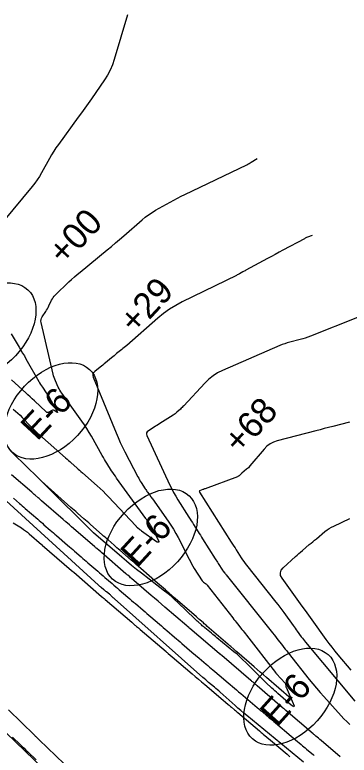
# Model space of a CAD drawing. Extents: x 1005228 to 1008882, y 1883389 to 1885754.
# Drawn here: x 1007166.4 to 1007247.3, y 1885273.6 to 1885452.9 of the extents above; entities that cross this region are included whole.
import ezdxf

# ---------------------------------------------------------------- set-up
doc = ezdxf.new("R2010")
doc.units = 0
for name, color, linetype in [('C-ANNO-NOTE', 7, 'Continuous'), ('R_Erosion', 7, 'Continuous'), ('S_BASELINE', 7, 'Continuous'), ('S_BRIDGE', 7, 'Continuous'), ('TSOBSTACLE', 7, 'Continuous')]:
    doc.layers.add(name, color=color, linetype=linetype)

msp = doc.modelspace()

# ---------------------------------------------------------------- linework, layer by layer
at = {"layer": 'C-ANNO-NOTE'}
for points in [[(1007193.66, 1885452.89), (1007190.46, 1885442.04), (1007190.02, 1885440.74), (1007189.48, 1885439.48), (1007188.84, 1885438.28), (1007188.1, 1885437.12), (1007184.96, 1885432.57), (1007184.17, 1885431.44), (1007183.37, 1885430.31), (1007182.57, 1885429.19), (1007181.75, 1885428.07), (1007176.93, 1885421.48), (1007176.35, 1885420.66), (1007175.8, 1885419.83), (1007175.28, 1885418.98), (1007174.78, 1885418.11), (1007172.83, 1885414.62), (1007172.33, 1885413.76), (1007171.78, 1885412.92), (1007171.2, 1885412.11), (1007170.59, 1885411.33), (1007163.58, 1885402.82)], [(1007166.02, 1885357.41), (1007166.58, 1885356.93), (1007167.14, 1885356.43), (1007167.67, 1885355.92), (1007168.19, 1885355.39), (1007170.24, 1885353.23), (1007170.76, 1885352.69), (1007171.28, 1885352.17), (1007171.83, 1885351.66), (1007172.38, 1885351.17), (1007178.7, 1885345.6), (1007179.04, 1885345.31), (1007179.38, 1885345.01), (1007179.72, 1885344.71), (1007180.05, 1885344.41), (1007181.4, 1885343.21), (1007181.73, 1885342.91), (1007182.07, 1885342.62), (1007182.41, 1885342.32), (1007182.74, 1885342.02), (1007186.34, 1885338.81), (1007187.05, 1885338.17), (1007187.74, 1885337.51), (1007188.41, 1885336.84), (1007189.07, 1885336.16), (1007195.67, 1885329.19), (1007195.7, 1885329.15), (1007195.74, 1885329.11), (1007195.77, 1885329.07), (1007195.8, 1885329.03), (1007195.93, 1885328.86), (1007195.96, 1885328.82), (1007196, 1885328.79), (1007196.04, 1885328.75), (1007196.08, 1885328.72), (1007196.64, 1885328.3), (1007196.75, 1885328.22), (1007196.86, 1885328.14), (1007196.97, 1885328.06), (1007197.08, 1885327.98), (1007200.65, 1885325.37), (1007200.71, 1885325.33), (1007200.78, 1885325.3), (1007200.84, 1885325.28), (1007200.92, 1885325.27), (1007201.21, 1885325.24), (1007201.27, 1885325.24), (1007201.3, 1885325.26), (1007201.31, 1885325.3), (1007201.29, 1885325.36), (1007199.48, 1885328.88), (1007199.39, 1885329.06), (1007199.28, 1885329.24), (1007199.17, 1885329.42), (1007199.05, 1885329.6), (1007198.57, 1885330.28), (1007198.45, 1885330.45), (1007198.32, 1885330.62), (1007198.2, 1885330.79), (1007198.08, 1885330.96), (1007191.04, 1885340.7), (1007190.73, 1885341.14), (1007190.42, 1885341.59), (1007190.12, 1885342.04), (1007189.83, 1885342.49), (1007188.66, 1885344.32), (1007188.37, 1885344.77), (1007188.09, 1885345.24), (1007187.82, 1885345.7), (1007187.55, 1885346.17), (1007184.95, 1885350.85), (1007184.41, 1885351.78), (1007183.85, 1885352.69), (1007183.27, 1885353.59), (1007182.65, 1885354.46), (1007177.76, 1885361.28), (1007177.52, 1885361.63), (1007177.3, 1885361.99), (1007177.1, 1885362.36), (1007176.92, 1885362.74), (1007176.22, 1885364.29), (1007176.05, 1885364.69), (1007175.91, 1885365.08), (1007175.78, 1885365.49), (1007175.68, 1885365.9), (1007172.77, 1885378.35), (1007172.72, 1885378.72), (1007172.74, 1885379.08), (1007172.84, 1885379.42), (1007173.02, 1885379.75), (1007173.87, 1885381.04), (1007174.08, 1885381.37), (1007174.28, 1885381.7), (1007174.46, 1885382.04), (1007174.63, 1885382.39), (1007175.3, 1885383.79), (1007175.48, 1885384.13), (1007175.69, 1885384.45), (1007175.92, 1885384.75), (1007176.19, 1885385.03), (1007179.5, 1885388.21), (1007180.15, 1885388.82), (1007180.82, 1885389.42), (1007181.49, 1885390.01), (1007182.17, 1885390.58), (1007188.74, 1885395.98), (1007189.76, 1885396.82), (1007190.76, 1885397.66), (1007191.76, 1885398.51), (1007192.76, 1885399.37), (1007197.19, 1885403.24), (1007197.96, 1885403.88), (1007198.76, 1885404.48), (1007199.6, 1885405.03), (1007200.46, 1885405.55), (1007203.97, 1885407.53), (1007204.85, 1885408.02), (1007205.74, 1885408.49), (1007206.63, 1885408.95), (1007207.54, 1885409.4), (1007222.54, 1885416.6), (1007222.81, 1885416.74), (1007223.07, 1885416.88), (1007223.32, 1885417.02), (1007223.57, 1885417.18), (1007225.07, 1885418.12)], [(1007238.33, 1885399.47), (1007237.2, 1885399.03), (1007237.01, 1885398.95), (1007236.83, 1885398.86), (1007236.65, 1885398.78), (1007236.47, 1885398.68), (1007231.27, 1885395.88), (1007230.34, 1885395.38), (1007229.42, 1885394.88), (1007228.49, 1885394.38), (1007227.57, 1885393.88), (1007222.31, 1885391.04), (1007222.12, 1885390.93), (1007221.93, 1885390.83), (1007221.74, 1885390.72), (1007221.55, 1885390.62), (1007220.79, 1885390.19), (1007220.6, 1885390.09), (1007220.41, 1885389.99), (1007220.22, 1885389.89), (1007220.03, 1885389.79), (1007206.93, 1885383.38), (1007205.35, 1885382.54), (1007203.83, 1885381.6), (1007202.38, 1885380.56), (1007200.99, 1885379.42), (1007193.47, 1885372.82), (1007193.17, 1885372.56), (1007192.87, 1885372.31), (1007192.57, 1885372.06), (1007192.26, 1885371.81), (1007191.03, 1885370.84), (1007190.72, 1885370.6), (1007190.42, 1885370.35), (1007190.12, 1885370.1), (1007189.82, 1885369.85), (1007188.37, 1885368.61), (1007188.04, 1885368.34), (1007187.72, 1885368.07), (1007187.39, 1885367.8), (1007187.06, 1885367.54), (1007185.73, 1885366.49), (1007185.46, 1885366.21), (1007185.31, 1885365.9), (1007185.29, 1885365.56), (1007185.39, 1885365.18), (1007190.89, 1885351.68), (1007191.38, 1885350.51), (1007191.9, 1885349.35), (1007192.45, 1885348.21), (1007193.02, 1885347.07), (1007196.19, 1885341.01), (1007196.37, 1885340.66), (1007196.56, 1885340.33), (1007196.76, 1885339.99), (1007196.97, 1885339.66), (1007197.95, 1885338.12), (1007198.09, 1885337.91), (1007198.23, 1885337.7), (1007198.37, 1885337.49), (1007198.52, 1885337.29), (1007199.11, 1885336.47), (1007199.25, 1885336.27), (1007199.4, 1885336.06), (1007199.55, 1885335.86), (1007199.69, 1885335.65), (1007203.47, 1885330.3), (1007204.14, 1885329.33), (1007204.76, 1885328.34), (1007205.35, 1885327.32), (1007205.9, 1885326.29), (1007208.58, 1885321.06), (1007208.88, 1885320.5), (1007209.18, 1885319.95), (1007209.5, 1885319.4), (1007209.83, 1885318.86), (1007211.7, 1885315.87), (1007211.78, 1885315.76), (1007211.87, 1885315.66), (1007211.97, 1885315.57), (1007212.08, 1885315.49), (1007212.54, 1885315.18), (1007212.65, 1885315.1), (1007212.75, 1885315.01), (1007212.85, 1885314.91), (1007212.93, 1885314.81), (1007219.15, 1885306.85), (1007219.42, 1885306.5), (1007219.7, 1885306.15), (1007219.98, 1885305.8), (1007220.25, 1885305.46), (1007221.36, 1885304.07), (1007221.64, 1885303.72), (1007221.92, 1885303.37), (1007222.19, 1885303.02), (1007222.47, 1885302.67), (1007229.49, 1885293.62), (1007229.51, 1885293.6), (1007229.53, 1885293.57), (1007229.55, 1885293.55), (1007229.57, 1885293.52), (1007229.66, 1885293.42), (1007229.68, 1885293.39), (1007229.7, 1885293.37), (1007229.72, 1885293.34), (1007229.74, 1885293.32), (1007231.81, 1885291.02), (1007231.86, 1885290.95), (1007231.89, 1885290.88), (1007231.92, 1885290.81), (1007231.93, 1885290.73), (1007231.95, 1885290.4), (1007231.96, 1885290.32), (1007231.97, 1885290.24), (1007232, 1885290.17), (1007232.03, 1885290.09), (1007233.78, 1885286.13), (1007233.97, 1885285.59), (1007233.95, 1885285.35), (1007233.72, 1885285.4), (1007233.26, 1885285.75), (1007230.07, 1885288.57), (1007229.7, 1885288.89), (1007229.33, 1885289.22), (1007228.97, 1885289.55), (1007228.61, 1885289.88), (1007227.17, 1885291.21), (1007226.81, 1885291.55), (1007226.46, 1885291.88), (1007226.11, 1885292.23), (1007225.76, 1885292.57), (1007222.31, 1885296.04), (1007221.61, 1885296.72), (1007220.89, 1885297.39), (1007220.16, 1885298.04), (1007219.41, 1885298.66), (1007215.27, 1885302.04), (1007214.94, 1885302.32), (1007214.61, 1885302.59), (1007214.28, 1885302.86), (1007213.95, 1885303.14), (1007212.39, 1885304.44), (1007212.18, 1885304.62), (1007211.98, 1885304.79), (1007211.77, 1885304.97), (1007211.57, 1885305.15), (1007210.76, 1885305.87), (1007210.56, 1885306.05), (1007210.36, 1885306.23), (1007210.16, 1885306.42), (1007209.96, 1885306.61), (1007205.82, 1885310.6), (1007205.06, 1885311.32), (1007204.28, 1885312.01), (1007203.47, 1885312.69), (1007202.65, 1885313.34), (1007197.02, 1885317.67), (1007195.81, 1885318.62), (1007194.61, 1885319.58), (1007193.43, 1885320.56), (1007192.27, 1885321.56), (1007185.47, 1885327.49), (1007185.38, 1885327.57), (1007185.28, 1885327.65), (1007185.19, 1885327.73), (1007185.1, 1885327.82), (1007184.74, 1885328.15), (1007184.64, 1885328.23), (1007184.56, 1885328.31), (1007184.47, 1885328.4), (1007184.38, 1885328.49), (1007174.55, 1885338.24), (1007173.41, 1885339.38), (1007172.26, 1885340.51), (1007171.12, 1885341.65), (1007169.97, 1885342.79), (1007165.21, 1885347.51)], [(1007249.28, 1885379.61), (1007237.91, 1885375.08), (1007237.3, 1885374.85), (1007236.69, 1885374.63), (1007236.08, 1885374.44), (1007235.45, 1885374.27), (1007232.95, 1885373.62), (1007232.33, 1885373.44), (1007231.71, 1885373.25), (1007231.11, 1885373.02), (1007230.51, 1885372.78), (1007216.68, 1885366.76), (1007215.48, 1885366.17), (1007214.37, 1885365.47), (1007213.33, 1885364.65), (1007212.38, 1885363.72), (1007207.26, 1885358.24), (1007207.07, 1885358.03), (1007206.87, 1885357.83), (1007206.67, 1885357.63), (1007206.46, 1885357.44), (1007205.64, 1885356.66), (1007205.43, 1885356.48), (1007205.21, 1885356.3), (1007204.98, 1885356.13), (1007204.75, 1885355.97), (1007201.48, 1885353.9), (1007201.14, 1885353.68), (1007200.79, 1885353.46), (1007200.45, 1885353.25), (1007200.1, 1885353.03), (1007198.72, 1885352.18), (1007198.44, 1885351.95), (1007198.29, 1885351.67), (1007198.26, 1885351.36), (1007198.37, 1885351.01), (1007203.92, 1885339.02), (1007204.36, 1885338.11), (1007204.83, 1885337.22), (1007205.33, 1885336.34), (1007205.85, 1885335.48), (1007208.54, 1885331.22), (1007208.82, 1885330.79), (1007209.09, 1885330.35), (1007209.37, 1885329.92), (1007209.64, 1885329.48), (1007210.74, 1885327.74), (1007211.02, 1885327.31), (1007211.29, 1885326.87), (1007211.57, 1885326.44), (1007211.84, 1885326), (1007214.89, 1885321.17), (1007215.07, 1885320.89), (1007215.25, 1885320.61), (1007215.42, 1885320.33), (1007215.6, 1885320.05), (1007216.64, 1885318.38), (1007216.65, 1885318.37), (1007216.66, 1885318.36), (1007216.67, 1885318.35), (1007216.68, 1885318.34), (1007216.72, 1885318.32), (1007216.73, 1885318.31), (1007216.74, 1885318.3), (1007216.75, 1885318.29), (1007216.75, 1885318.28), (1007217.21, 1885317.7), (1007217.29, 1885317.6), (1007217.37, 1885317.5), (1007217.45, 1885317.4), (1007217.53, 1885317.3), (1007228.43, 1885303.64), (1007228.78, 1885303.21), (1007229.12, 1885302.78), (1007229.46, 1885302.34), (1007229.8, 1885301.9), (1007231.16, 1885300.16), (1007231.5, 1885299.72), (1007231.84, 1885299.28), (1007232.19, 1885298.85), (1007232.53, 1885298.42), (1007237.65, 1885291.98), (1007238.51, 1885290.91), (1007239.39, 1885289.86), (1007240.28, 1885288.82), (1007241.18, 1885287.8), (1007245.34, 1885283.17), (1007246.02, 1885282.44), (1007246.72, 1885281.74), (1007247.44, 1885281.06)], [(1007165.51, 1885375.64), (1007167.45, 1885372.41), (1007167.87, 1885371.7), (1007168.28, 1885370.99), (1007168.7, 1885370.28), (1007169.1, 1885369.56), (1007172.19, 1885364.09), (1007172.39, 1885363.74), (1007172.61, 1885363.39), (1007172.83, 1885363.05), (1007173.07, 1885362.72), (1007174.02, 1885361.39), (1007174.25, 1885361.05), (1007174.48, 1885360.71), (1007174.69, 1885360.36), (1007174.9, 1885360.01), (1007176.68, 1885356.81), (1007176.74, 1885356.68), (1007176.73, 1885356.62), (1007176.67, 1885356.62), (1007176.55, 1885356.69), (1007175.94, 1885357.07), (1007175.79, 1885357.14), (1007175.64, 1885357.17), (1007175.48, 1885357.15), (1007175.33, 1885357.08), (1007174.64, 1885356.67), (1007174.47, 1885356.6), (1007174.32, 1885356.59), (1007174.16, 1885356.63), (1007174.02, 1885356.74), (1007171.16, 1885359.39), (1007170.63, 1885359.87), (1007170.1, 1885360.36), (1007169.58, 1885360.84), (1007169.05, 1885361.32), (1007165.57, 1885364.47)], [(1007236.23, 1885271.89), (1007222.57, 1885283.19), (1007221.84, 1885283.8), (1007221.11, 1885284.42), (1007220.39, 1885285.04), (1007219.68, 1885285.67), (1007216.1, 1885288.87), (1007215.76, 1885289.17), (1007215.41, 1885289.47), (1007215.06, 1885289.77), (1007214.71, 1885290.07), (1007213.3, 1885291.25), (1007212.94, 1885291.55), (1007212.6, 1885291.85), (1007212.25, 1885292.15), (1007211.9, 1885292.45), (1007190.53, 1885311.45), (1007190.43, 1885311.55), (1007190.33, 1885311.64), (1007190.22, 1885311.74), (1007190.12, 1885311.83), (1007189.72, 1885312.22), (1007189.62, 1885312.32), (1007189.51, 1885312.41), (1007189.41, 1885312.5), (1007189.3, 1885312.58), (1007188.55, 1885313.16), (1007188.39, 1885313.29), (1007188.23, 1885313.42), (1007188.07, 1885313.55), (1007187.92, 1885313.68), (1007187.3, 1885314.22), (1007187.14, 1885314.35), (1007186.99, 1885314.49), (1007186.84, 1885314.63), (1007186.68, 1885314.77), (1007162.39, 1885336.88)], [(1007247.78, 1885294.21), (1007244.67, 1885297.92), (1007243.92, 1885298.84), (1007243.19, 1885299.76), (1007242.47, 1885300.7), (1007241.77, 1885301.66), (1007238.35, 1885306.4), (1007237.55, 1885307.51), (1007236.75, 1885308.62), (1007235.95, 1885309.73), (1007235.15, 1885310.84), (1007231.08, 1885316.47), (1007230.72, 1885317.15), (1007230.65, 1885317.8), (1007230.86, 1885318.41), (1007231.35, 1885319), (1007234.31, 1885321.7), (1007234.72, 1885322.07), (1007235.14, 1885322.43), (1007235.56, 1885322.8), (1007235.98, 1885323.16), (1007237.66, 1885324.6), (1007238.09, 1885324.95), (1007238.51, 1885325.31), (1007238.93, 1885325.67), (1007239.36, 1885326.02), (1007241.45, 1885327.76), (1007241.95, 1885328.15), (1007242.48, 1885328.5), (1007243.02, 1885328.82), (1007243.59, 1885329.11), (1007247.48, 1885330.92)], [(1007189.17, 1885255.05), (1007164.33, 1885279.04)]]:
    msp.add_lwpolyline(points, dxfattribs=at)
at = {"layer": 'R_Erosion'}
for centre, major_axis in [((1007160.18, 1885376.33), (9.37, 9.99)), ((1007175.15, 1885356.98), (9.32, 10.04)), ((1007199.3, 1885326.35), (9.25, 10.1)), ((1007233.05, 1885287.78), (9.16, 10.19))]:
    msp.add_ellipse(centre, major_axis=major_axis, ratio=0.638788, dxfattribs=at)
at = {"layer": 'S_BRIDGE'}
msp.add_lwpolyline([(1007247.41, 1885354.29), (1007243.32, 1885353.23), (1007242.3, 1885352.96), (1007241.28, 1885352.7), (1007240.26, 1885352.43), (1007239.24, 1885352.17), (1007229.9, 1885349.73), (1007228.98, 1885349.42), (1007228.15, 1885348.98), (1007227.4, 1885348.42), (1007226.73, 1885347.73), (1007223.3, 1885343.65), (1007223.11, 1885343.43), (1007222.91, 1885343.22), (1007222.7, 1885343.03), (1007222.48, 1885342.84), (1007221.32, 1885341.9), (1007221.23, 1885341.83), (1007221.14, 1885341.75), (1007221.06, 1885341.68), (1007220.97, 1885341.6), (1007220.65, 1885341.28), (1007220.56, 1885341.21), (1007220.47, 1885341.15), (1007220.37, 1885341.09), (1007220.27, 1885341.05), (1007212.45, 1885338.14), (1007212.31, 1885338.09), (1007212.17, 1885338.04), (1007212.03, 1885337.98), (1007211.89, 1885337.92), (1007211.09, 1885337.59), (1007211.08, 1885337.58), (1007211.07, 1885337.58), (1007211.06, 1885337.57), (1007211.05, 1885337.57), (1007211.01, 1885337.55), (1007211, 1885337.54), (1007211, 1885337.53), (1007211, 1885337.52), (1007211, 1885337.51), (1007211.05, 1885337.41), (1007211.05, 1885337.41), (1007211.05, 1885337.4), (1007211.06, 1885337.39), (1007211.06, 1885337.38), (1007211.11, 1885337.32), (1007218.78, 1885325.2), (1007219.08, 1885324.73), (1007219.38, 1885324.26), (1007219.68, 1885323.79), (1007219.98, 1885323.32), (1007221.17, 1885321.43), (1007221.47, 1885320.96), (1007221.79, 1885320.5), (1007222.11, 1885320.06), (1007222.46, 1885319.62), (1007229.58, 1885310.69), (1007230.06, 1885310.07), (1007230.54, 1885309.44), (1007231.01, 1885308.81), (1007231.48, 1885308.18), (1007233.75, 1885305.03), (1007233.99, 1885304.69), (1007234.24, 1885304.35), (1007234.49, 1885304.01), (1007234.73, 1885303.67), (1007235.72, 1885302.3), (1007235.97, 1885301.96), (1007236.23, 1885301.62), (1007236.49, 1885301.29), (1007236.75, 1885300.97), (1007248.68, 1885286.73)], dxfattribs=at)
at = {"layer": 'TSOBSTACLE'}
for points in [[(1007245.13, 1885273.2), (1007240.49, 1885277.16), (1007240.17, 1885277.44), (1007239.85, 1885277.71), (1007239.21, 1885278.25), (1007239.05, 1885278.39), (1007238.9, 1885278.53), (1007238.74, 1885278.66), (1007238.58, 1885278.8), (1007231.95, 1885284.48), (1007231.47, 1885284.89), (1007231.41, 1885284.95), (1007231.34, 1885285.01), (1007231.27, 1885285.06), (1007231.2, 1885285.12), (1007225.05, 1885290.41), (1007224.92, 1885290.52), (1007224.8, 1885290.63), (1007224.67, 1885290.74), (1007224.54, 1885290.85), (1007224.04, 1885291.27), (1007223.91, 1885291.38), (1007223.78, 1885291.49), (1007223.66, 1885291.6), (1007223.53, 1885291.7), (1007216.45, 1885297.73), (1007216.26, 1885297.89), (1007216.2, 1885297.94), (1007216.14, 1885297.99), (1007215.87, 1885298.22), (1007208.75, 1885304.3), (1007208.69, 1885304.35), (1007208.62, 1885304.4), (1007208.56, 1885304.46), (1007208.5, 1885304.51), (1007208.19, 1885304.78), (1007208, 1885304.94), (1007202.72, 1885309.46), (1007201.89, 1885310.17), (1007201.06, 1885310.88), (1007200.23, 1885311.6), (1007199.4, 1885312.31), (1007194.64, 1885316.39), (1007194.42, 1885316.59), (1007194.19, 1885316.79), (1007193.73, 1885317.18), (1007193.62, 1885317.27), (1007193.51, 1885317.37), (1007193.39, 1885317.47), (1007193.28, 1885317.57), (1007187.37, 1885322.66), (1007187.09, 1885322.9), (1007186.81, 1885323.15), (1007186.24, 1885323.63), (1007186.1, 1885323.75), (1007185.96, 1885323.88), (1007185.82, 1885324), (1007185.68, 1885324.12), (1007180.12, 1885328.94), (1007179.61, 1885329.37), (1007178.77, 1885330.1), (1007178.6, 1885330.25), (1007178.43, 1885330.39), (1007178.26, 1885330.54), (1007178.09, 1885330.69), (1007172.87, 1885335.23), (1007172.67, 1885335.4), (1007172.47, 1885335.57), (1007172.28, 1885335.74), (1007172.08, 1885335.91), (1007171.3, 1885336.59), (1007171.11, 1885336.76), (1007170.91, 1885336.93), (1007170.72, 1885337.1), (1007170.52, 1885337.27), (1007165.63, 1885341.53)], [(1007233.27, 1885287.3), (1007227.32, 1885292.42), (1007226.56, 1885293.07), (1007225.8, 1885293.73), (1007225.04, 1885294.38), (1007224.28, 1885295.04), (1007220.08, 1885298.66), (1007219.9, 1885298.82), (1007219.72, 1885298.97), (1007219.54, 1885299.13), (1007219.36, 1885299.29), (1007218.63, 1885299.91), (1007218.45, 1885300.07), (1007218.27, 1885300.23), (1007218.09, 1885300.38), (1007217.91, 1885300.54), (1007212.9, 1885304.88), (1007212.68, 1885305.07), (1007212.47, 1885305.25), (1007212.25, 1885305.44), (1007212.04, 1885305.63), (1007211.18, 1885306.37), (1007210.96, 1885306.56), (1007210.75, 1885306.74), (1007210.53, 1885306.93), (1007210.32, 1885307.12), (1007205.2, 1885311.57), (1007204.81, 1885311.91), (1007204.42, 1885312.25), (1007203.63, 1885312.93), (1007203.43, 1885313.1), (1007203.24, 1885313.27), (1007203.04, 1885313.44), (1007202.85, 1885313.62), (1007201.87, 1885314.47), (1007201.41, 1885314.87), (1007200.96, 1885315.26), (1007196.9, 1885318.81), (1007196.32, 1885319.31), (1007195.74, 1885319.82), (1007195.16, 1885320.32), (1007194.59, 1885320.83), (1007191.84, 1885323.23), (1007191.48, 1885323.54), (1007191.12, 1885323.86), (1007190.76, 1885324.17), (1007190.41, 1885324.48), (1007188.97, 1885325.74), (1007188.61, 1885326.06), (1007188.25, 1885326.37), (1007187.89, 1885326.69), (1007187.53, 1885327), (1007184.69, 1885329.5), (1007184.3, 1885329.85), (1007183.91, 1885330.19), (1007183.52, 1885330.53), (1007183.12, 1885330.88), (1007181.56, 1885332.25), (1007181.17, 1885332.6), (1007180.78, 1885332.94), (1007180.39, 1885333.29), (1007179.99, 1885333.63), (1007173.64, 1885339.23), (1007173.38, 1885339.46), (1007173.31, 1885339.52), (1007173.24, 1885339.58), (1007172.85, 1885339.93)], [(1007166.09, 1885335.83), (1007167.49, 1885334.6), (1007167.84, 1885334.3), (1007168.2, 1885333.99), (1007168.55, 1885333.68), (1007168.9, 1885333.38), (1007171.93, 1885330.75), (1007172.3, 1885330.42), (1007172.68, 1885330.09), (1007173.06, 1885329.76), (1007173.44, 1885329.43), (1007174.96, 1885328.11), (1007175.34, 1885327.78), (1007175.72, 1885327.45), (1007176.1, 1885327.12), (1007176.48, 1885326.79), (1007179.18, 1885324.46), (1007179.59, 1885324.1), (1007180, 1885323.75), (1007180.4, 1885323.4), (1007180.81, 1885323.05), (1007182.44, 1885321.64), (1007182.85, 1885321.28), (1007183.26, 1885320.93), (1007183.67, 1885320.58), (1007184.07, 1885320.23), (1007186.45, 1885318.18), (1007186.88, 1885317.8), (1007187.32, 1885317.43), (1007187.76, 1885317.05), (1007188.19, 1885316.67), (1007189.93, 1885315.17), (1007190.37, 1885314.8), (1007190.81, 1885314.42), (1007191.24, 1885314.05), (1007191.68, 1885313.67), (1007193.73, 1885311.91), (1007194.19, 1885311.51), (1007194.65, 1885311.11), (1007195.12, 1885310.71), (1007195.58, 1885310.32), (1007197.44, 1885308.72), (1007197.9, 1885308.32), (1007198.36, 1885307.93), (1007198.83, 1885307.53), (1007199.29, 1885307.13), (1007201.4, 1885305.32), (1007201.86, 1885304.93), (1007202.31, 1885304.55), (1007202.76, 1885304.16), (1007203.22, 1885303.77), (1007205.03, 1885302.22), (1007205.48, 1885301.83), (1007205.93, 1885301.44), (1007206.39, 1885301.06), (1007206.84, 1885300.67), (1007209.27, 1885298.6), (1007210.12, 1885297.87), (1007210.97, 1885297.15), (1007212.71, 1885295.66), (1007213.11, 1885295.32), (1007213.51, 1885294.97), (1007213.91, 1885294.63), (1007214.31, 1885294.29), (1007216.32, 1885292.59), (1007217.52, 1885291.57), (1007220.01, 1885289.45), (1007220.56, 1885288.99), (1007221.11, 1885288.52), (1007221.65, 1885288.05), (1007222.2, 1885287.59), (1007225.04, 1885285.19), (1007225.41, 1885284.88), (1007225.77, 1885284.56), (1007226.14, 1885284.25), (1007226.51, 1885283.94), (1007227.97, 1885282.7), (1007228.34, 1885282.39), (1007228.71, 1885282.08), (1007229.07, 1885281.77), (1007229.44, 1885281.46), (1007233.28, 1885278.22), (1007234.29, 1885277.36), (1007235.68, 1885276.19), (1007236, 1885275.92), (1007236.32, 1885275.65), (1007236.64, 1885275.38), (1007236.96, 1885275.11), (1007238.23, 1885274.04), (1007238.55, 1885273.77), (1007238.87, 1885273.51)], [(1007165.98, 1885329.88), (1007167.99, 1885328.63), (1007168.49, 1885328.3), (1007168.97, 1885327.96), (1007169.43, 1885327.6), (1007169.89, 1885327.22), (1007172.86, 1885324.64), (1007173, 1885324.52), (1007173.04, 1885324.49), (1007180.13, 1885318.35), (1007180.47, 1885318.06), (1007180.51, 1885318.02), (1007180.55, 1885317.98), (1007180.59, 1885317.95), (1007180.64, 1885317.91), (1007187.41, 1885312.07), (1007187.69, 1885311.83), (1007187.97, 1885311.59), (1007188.04, 1885311.53), (1007188.11, 1885311.47), (1007188.17, 1885311.41), (1007188.24, 1885311.35), (1007194.7, 1885305.8), (1007194.99, 1885305.55), (1007195.47, 1885305.14), (1007195.57, 1885305.05), (1007195.67, 1885304.97), (1007195.77, 1885304.89), (1007195.86, 1885304.8), (1007196.29, 1885304.44), (1007196.5, 1885304.26), (1007196.7, 1885304.08), (1007202.98, 1885298.71), (1007203.11, 1885298.6), (1007203.24, 1885298.48), (1007203.38, 1885298.37), (1007203.51, 1885298.26), (1007204.44, 1885297.46), (1007209.29, 1885293.32), (1007210.06, 1885292.66), (1007210.83, 1885292.01), (1007211.6, 1885291.35), (1007212.37, 1885290.7), (1007216.8, 1885286.93), (1007217.34, 1885286.47), (1007218.06, 1885285.86), (1007218.25, 1885285.7), (1007218.43, 1885285.55), (1007218.61, 1885285.4), (1007218.79, 1885285.24), (1007219.58, 1885284.57), (1007219.77, 1885284.41), (1007219.96, 1885284.25), (1007220.15, 1885284.09), (1007220.34, 1885283.92), (1007225.59, 1885279.48), (1007225.81, 1885279.29), (1007226.03, 1885279.1), (1007226.25, 1885278.92), (1007226.48, 1885278.73), (1007228.25, 1885277.23), (1007232.27, 1885273.83), (1007232.96, 1885273.25)], [(1007178.3, 1885271.55), (1007172.32, 1885277.32), (1007172.03, 1885277.61), (1007171.53, 1885278.08), (1007171.44, 1885278.18), (1007171.34, 1885278.27), (1007171.24, 1885278.37), (1007171.14, 1885278.47), (1007164.84, 1885284.58)], [(1007165.86, 1885278.02), (1007167.72, 1885276.21), (1007168.18, 1885275.76), (1007168.64, 1885275.32), (1007169.1, 1885274.87), (1007169.56, 1885274.43), (1007171.55, 1885272.51)]]:
    msp.add_lwpolyline(points, dxfattribs=at)

# ---------------------------------------------------------------- texts
at = {"layer": 'R_Erosion'}
for rotation, p in [(47.1442, (1007171.83, 1885349.48)), (47.5319, (1007196.03, 1885318.83)), (48.044, (1007229.84, 1885280.23))]:
    msp.add_text('E-6', height=6.25, rotation=rotation, dxfattribs=at).set_placement(p)
at = {"layer": 'S_BASELINE'}
for s, rotation, p in [('+00', 46.8499, (1007178.33, 1885391.93)), ('+29', 47.1442, (1007195.57, 1885375.26)), ('+68', 47.5319, (1007220.83, 1885346.19))]:
    msp.add_text(s, height=6.25, rotation=rotation, dxfattribs=at).set_placement(p)

doc.saveas('drawing.dxf')
